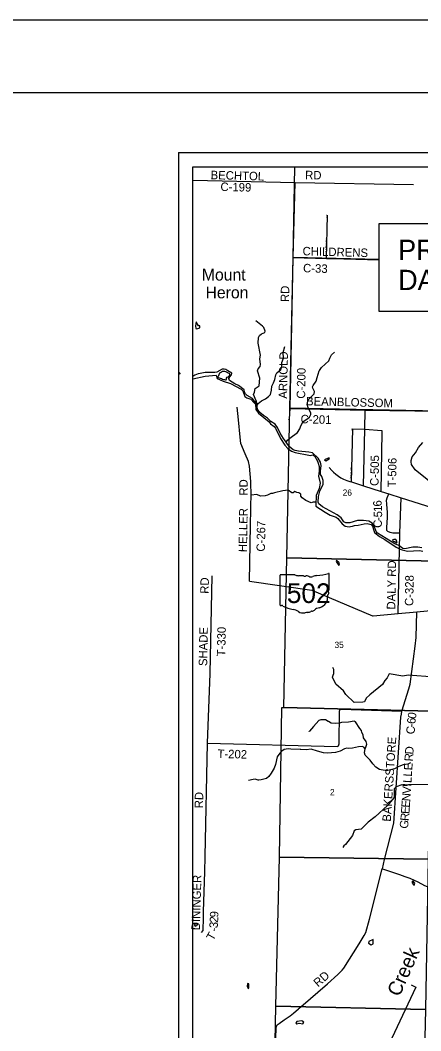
# Model space of a CAD drawing. Extents: x -784 to 1375, y -225 to 440.
# Drawn here: x 215.1 to 270.5, y 300.2 to 440 of the extents above; entities that cross this region are included whole.
import ezdxf

# ---------------------------------------------------------------- set-up
doc = ezdxf.new("R2010")
doc.units = 0
for name, color, linetype in [('GM_X_County_Road', 7, 'Continuous'), ('GM_X_County_Road_Text', 7, 'Continuous'), ('GM_X_County_Subdivision', 7, 'Continuous'), ('GM_X_County_Subdivision_Text', 7, 'Continuous'), ('GM_X_Major_River', 7, 'Continuous'), ('GM_X_Minor_Lake', 7, 'Continuous'), ('GM_X_Minor_River', 7, 'Continuous'), ('GM_X_Minor_River_Text', 7, 'Continuous'), ('GM_X_Section', 7, 'Continuous'), ('GM_X_Section_Text', 7, 'Continuous'), ('GM_X_State_Location', 7, 'Continuous'), ('GM_X_State_Route', 7, 'Continuous'), ('GM_X_State_Shield', 7, 'Continuous'), ('GM_X_Township_Road', 7, 'Continuous'), ('GM_X_Township_Road_Text', 7, 'Continuous'), ('GM_X_Township_Subdivision', 7, 'Continuous'), ('GM_X_Township_Subdivision_Text', 7, 'Continuous'), ('GM_X_Unincorporated_Text', 7, 'Continuous'), ('SH_Border', 7, 'Continuous'), ('SH_Cut_Line', 7, 'Continuous'), ('SH_Data', 7, 'Continuous'), ('SH_Text', 7, 'Continuous')]:
    doc.layers.add(name, color=color, linetype=linetype)

msp = doc.modelspace()

# ---------------------------------------------------------------- linework, layer by layer
at = {"layer": 'GM_X_County_Road'}
msp.add_line((258.21, 407.02), (264.75, 406.84), dxfattribs=at)
for points in [[(238.96, 417.89), (253.09, 417.56), (269.46, 417.26)], [(252.23, 384.67), (252.32, 384.82), (252.4, 386.29), (252.84, 407.18), (253.09, 417.56)], [(252.84, 407.18), (257.42, 407.04), (258.21, 407.02), (258.21, 407.02)], [(246.81, 362.4), (246.93, 370.09), (247.01, 374.7), (246.99, 375.62), (246.99, 376.17), (246.79, 378.31), (246.65, 378.96), (246.18, 380.02), (245.58, 381.44), (245.49, 382.33), (245.28, 384.72), (245.08, 386.47)], [(252.4, 386.29), (262.79, 386.04), (273.08, 385.89), (283.53, 385.61)], [(262.58, 375.57), (262.75, 383.41), (262.79, 386.04)], [(267.58, 369.03), (266.61, 369.04), (266.26, 369.11), (265.95, 369.28), (265.8, 369.39), (265.8, 369.83), (265.87, 371.18), (265.86, 371.9), (265.78, 373.04), (265.73, 373.58), (265.82, 373.94), (266.06, 374.48)], [(267.37, 357.91), (267.58, 369.03), (267.75, 373.93)], [(265.18, 322.58), (265.46, 323.89), (266.77, 328.89), (267.74, 343.59), (267.82, 343.99), (267.88, 344.4), (268.82, 347.5), (269, 348.12), (269.69, 353.42), (269.85, 354.58), (269.94, 358.16)], [(253.64, 303.3), (253.88, 303.51), (257.58, 306.7), (258.99, 307.97), (259.63, 308.56), (259.86, 308.84), (261.96, 312.21), (262.66, 313.36), (262.87, 313.77), (263.4, 315.64), (265.15, 322.57), (265.18, 322.58), (267.52, 321.79), (268.28, 321.53), (268.96, 321.29), (269.55, 321.03), (270.07, 320.79), (271.02, 320.31), (271.59, 320.05), (272.07, 319.91), (278.91, 319.43)], [(250.27, 293.21), (250.49, 300.64), (250.51, 300.8), (250.62, 301), (250.89, 301.21), (251.6, 301.69), (252.41, 302.27), (252.86, 302.63), (253.55, 303.23), (253.64, 303.3)]]:
    msp.add_lwpolyline(points, dxfattribs=at)
at = {"layer": 'GM_X_County_Subdivision'}
msp.add_lwpolyline([(257.42, 407.04), (257.59, 413.01)], dxfattribs=at)
at = {"layer": 'GM_X_Major_River'}
for p, q in [((237, 391.27), (237.19, 391.01)), ((247.75, 386.98), (247.55, 387.18))]:
    msp.add_line(p, q, dxfattribs=at)
for points in [[(247.55, 387.18), (247.19, 387.67), (246.45, 388.09), (246.22, 388.31), (246.12, 388.58), (246.05, 388.84), (245.27, 389.45), (244.77, 389.69), (244.03, 390.16), (243.92, 390.42), (244.06, 390.67), (244.31, 390.92), (244.36, 391.16), (243.81, 391.48), (243.53, 391.66), (243.28, 391.73), (243.01, 391.72), (242.25, 391.29), (241.98, 391.24), (240.68, 391.24), (239.96, 391.13), (239.7, 391.06), (239.23, 390.9), (238.96, 390.69)], [(238.96, 390.4), (240.66, 390.74), (242.18, 390.9), (242.32, 390.44), (243.14, 390.08), (244.16, 389.74), (245.64, 388.96), (245.87, 388.72), (246.15, 387.96), (246.43, 387.77), (246.96, 387.59), (247.41, 387.13), (247.6, 386.88), (247.66, 386.16), (248.02, 385.64), (249.53, 384.44), (249.71, 384.18), (250.2, 383.81), (250.4, 383.58), (251.09, 382.12), (251.66, 381.19), (252.11, 380.74), (252.59, 380.4), (253.12, 380.19), (254.99, 379.81), (255.25, 379.78), (255.53, 379.88), (255.76, 379.71), (256.18, 379), (256.31, 378.72), (256.42, 378.24), (256.45, 377.67), (256.34, 376.91), (256.55, 375.95), (256.45, 375.2), (256.01, 374.24), (255.95, 372.97), (255.99, 372.75), (257.24, 371.95), (257.96, 371.53), (258.8, 371.24), (259.02, 371.08), (259.6, 370.32), (260.04, 370.01), (260.57, 369.92), (260.78, 369.94), (261.03, 370.01), (261.32, 370.11), (261.83, 370.15), (262.65, 370.34), (263.09, 370.36), (263.64, 370.21), (263.8, 369.99), (263.99, 369.38), (264.09, 369.14), (264.78, 368.56), (265.5, 368.16), (267.06, 367.11), (267.64, 366.84), (267.92, 366.71), (268.67, 366.53), (270.29, 366.63), (270.79, 366.55)], [(244.08, 391.09), (243.87, 391.17), (243.76, 391.22), (243.62, 391.29), (243.51, 391.36), (243.39, 391.4), (243.23, 391.41), (243.06, 391.38), (242.94, 391.31), (242.77, 391.22), (242.65, 391.16), (242.58, 391.06), (242.53, 390.96), (242.49, 390.82), (242.47, 390.72), (242.42, 390.65), (242.43, 390.55), (242.59, 390.5), (242.74, 390.46), (242.9, 390.41), (243.05, 390.35), (243.2, 390.29), (243.35, 390.27)], [(243.35, 390.27), (243.46, 390.24), (243.56, 390.26), (243.61, 390.35), (243.63, 390.47), (243.68, 390.6), (243.82, 390.67), (243.91, 390.74), (244, 390.82), (244.05, 390.9), (244.08, 391.09)], [(247.75, 386.98), (247.55, 387.18), (247.71, 387.34)], [(247.71, 387.34), (247.75, 386.98)], [(256.9, 372.66), (256.39, 373.08), (256.3, 373.34), (256.34, 374.12), (256.53, 374.86), (257, 375.81), (256.98, 376.31), (256.78, 376.88), (256.63, 377.15), (256.62, 377.61), (256.71, 378.39), (256.59, 378.84), (256.29, 379.41), (255.52, 380.13), (254.99, 380.25), (253.56, 380.39), (253.1, 380.46), (252.81, 380.57), (252.27, 381.03), (251.65, 381.94), (251.51, 382.14), (251.02, 382.86), (250.66, 383.66), (250.32, 384.12), (249.74, 384.47), (249.27, 384.95), (248.74, 385.33), (248.2, 385.72), (247.92, 386.21), (247.79, 386.93), (247.75, 386.98)], [(270.61, 367), (270.09, 367.1), (269.38, 367.08), (268.3, 366.87), (268.02, 366.92), (267.47, 367.34), (266.91, 367.54), (264.49, 369.05), (264.3, 369.26), (264.09, 369.9), (263.76, 370.42), (263.55, 370.56), (263.31, 370.67), (262.55, 370.79), (261.75, 370.77), (260.69, 370.45), (260.11, 370.47), (259.84, 370.62), (259.46, 371.16), (258.93, 371.57), (256.9, 372.66)]]:
    msp.add_lwpolyline(points, dxfattribs=at)
at = {"layer": 'GM_X_Minor_Lake'}
for points in [[(239.43, 398.29), (239.31, 397.72), (239.35, 397.35), (239.49, 397.31), (239.9, 397.45)], [(239.9, 397.45), (239.93, 397.71), (239.73, 397.71), (239.43, 398.29)], [(257.82, 379.3), (257.84, 379.42), (257.69, 379.42), (257.17, 379.16)], [(257.17, 379.16), (257.37, 379.06), (257.82, 379.3)], [(267.02, 368.14), (266.75, 368.17), (266.59, 368.11), (266.65, 367.94), (266.91, 367.88)], [(266.91, 367.88), (267.13, 367.68), (267.21, 367.83), (267.02, 368.14)], [(258.84, 365.23), (258.8, 365.11), (259.14, 364.57)], [(259.14, 364.57), (259.25, 364.75), (259.2, 364.93), (258.84, 365.23)], [(269.37, 320.93), (269.24, 320.75), (269.47, 320.39), (269.59, 320.33)], [(269.59, 320.33), (269.64, 320.59), (269.37, 320.93)], [(239.51, 315.02), (239.12, 314.87), (239.28, 314.64)], [(239.28, 314.64), (239.6, 314.78), (239.51, 315.02)], [(263.24, 312.31), (263.61, 312.08), (263.88, 312.21), (263.89, 312.81)], [(263.89, 312.81), (263.3, 312.53), (263.24, 312.31)], [(246.72, 306.7), (246.52, 306.75), (246.45, 306.38), (246.61, 306.03)], [(246.61, 306.03), (246.68, 306.1), (246.72, 306.7)], [(254.29, 301.4), (254.03, 301.57), (253.34, 301.46), (253.2, 301.22)], [(253.2, 301.22), (253.33, 301.17), (253.68, 301.26), (254.16, 301.16), (254.29, 301.4)]]:
    msp.add_lwpolyline(points, dxfattribs=at)
at = {"layer": 'GM_X_Minor_River'}
for points in [[(248.01, 391.76), (248.26, 392.11), (248.3, 392.38), (248.23, 393.14), (248.3, 393.66), (247.98, 395.3), (248.02, 396.11), (248.19, 396.39), (248.45, 396.62), (248.89, 396.78), (248.96, 396.98), (248.77, 397.47), (248.61, 397.68), (247.68, 398.39)], [(251.14, 391.69), (251.25, 392.1), (251.26, 392.63), (251.51, 393.26), (251.46, 394.01), (251.67, 394.87)], [(256.46, 391.56), (256.74, 391.93), (257.75, 392.87), (257.91, 393.23), (257.94, 393.35), (258.15, 393.69), (258.54, 394.08)], [(247.71, 387.34), (247.33, 388.2), (247.49, 388.53), (247.59, 389.06), (248.12, 389.41), (248.24, 390.48), (247.88, 391.49), (248.01, 391.76)], [(247.83, 386.73), (248.01, 386.97), (248.47, 387.36), (249.01, 387.64), (249.42, 387.94), (249.71, 388.23), (249.84, 388.82), (249.88, 389.38), (250.11, 389.83), (250.29, 390.29), (250.44, 390.96), (250.57, 391.2), (251.14, 391.69)], [(251.87, 381.6), (252.03, 381.89), (252.39, 382.18), (253.42, 382.95), (253.74, 383.47), (253.89, 383.88), (254.21, 384.46), (254.74, 384.82), (255.09, 385.08), (255.26, 385.43), (255.26, 385.67), (254.9, 386.39), (254.79, 386.82), (254.87, 387.29), (255.06, 387.66), (255.19, 387.77), (255.24, 387.82), (255.72, 388.33), (255.78, 388.63), (255.53, 389.1), (255.52, 389.28), (255.61, 389.45), (256.02, 390.05), (256.17, 390.56), (256.44, 391.47), (256.46, 391.56)], [(273.03, 375.13), (269.69, 377.79), (269.2, 378.55), (269.14, 378.89), (269.14, 379.1), (269.3, 379.59), (269.75, 380.16), (270.15, 380.89), (270.79, 381.59)], [(255.97, 373.33), (255.61, 373.34), (255.34, 373.23), (254.57, 373.57), (254.07, 373.9), (253.91, 374.17), (253.91, 374.45), (253.62, 374.59), (253.35, 374.64), (253.08, 374.81), (252.83, 374.63), (252.63, 374.6), (252.14, 374.99), (251.42, 374.9), (250.26, 374.63), (249.99, 374.51), (249.73, 374.51), (249.26, 374.31), (248.96, 374.18), (248.34, 374.13), (247.75, 374.36), (247.05, 374.3)], [(283.47, 347.41), (278.09, 347.44), (278.04, 348.56), (272.49, 348.8), (272.38, 349.1), (268.73, 349.39), (267.98, 349.26), (266.12, 349.59), (265.83, 349.02), (265.5, 348.67), (265.18, 348.08), (263.45, 346.68), (262.95, 346.19), (262.71, 345.72), (262.45, 345.64), (261.28, 345.61), (260.13, 346.69), (259.81, 347.22), (258.74, 348.12), (258.28, 349.09), (258.37, 349.4), (258.46, 349.61), (258.47, 350.17), (258.31, 350.46)], [(269.07, 337.25), (268.71, 337.06), (268.05, 336.96), (267.43, 336.74), (266.84, 336.41), (265.92, 336.21), (265.56, 336.19), (265.02, 336.28), (264.76, 336.34), (264.27, 336.65), (263.83, 337.12), (263.47, 337.63), (262.79, 338.34), (262.72, 338.64), (262.8, 339.23), (262.83, 339.27), (263.02, 339.83), (262.94, 340.19), (262.57, 340.73), (262.52, 341.12), (262.32, 341.46), (262.29, 341.73), (262.07, 342), (261.45, 342.92), (261.29, 343.02), (260.48, 342.88), (259.53, 342.85), (259.26, 342.74), (258.72, 342.69), (258.09, 342.76), (257.72, 342.96), (257.66, 342.99), (257.32, 343.2), (256.67, 343.21), (256.4, 343.12), (255.66, 342.29), (255.07, 341.64), (255.06, 341.59), (255.04, 341.63)], [(262.8, 339.19), (262.6, 339.44), (262.4, 339.54), (261.87, 339.45), (261.05, 339.29), (260.51, 339.25), (260.26, 339.29), (259.92, 339.2), (259.33, 338.87), (258.67, 338.68), (257.58, 338.6), (257.05, 338.63), (256.19, 338.87), (255.32, 339.16), (254.61, 339.07), (253.87, 339.11), (253.82, 339.1), (252.52, 339.17), (252.12, 339.18), (251.58, 339.1), (251.25, 338.88), (250.98, 338.6), (250.63, 338.08), (250.39, 337.05), (250.19, 336.51), (249.79, 335.85), (249.47, 335.37), (249.15, 335.1), (248.41, 334.9), (248.08, 334.87), (248.01, 334.88), (247.59, 335.01), (247.29, 334.96), (246.64, 334.8)], [(276.95, 334.07), (271.69, 334.25), (268.78, 334.23), (268.52, 334.1), (268.09, 334.1), (267.85, 334.22), (267.06, 333.96), (266.81, 333.68), (266.81, 333.03), (266.8, 332.45), (265.87, 331.35), (264.17, 329.8), (263.2, 329.03), (262.25, 328.1), (261.52, 328.01), (261.27, 327.87), (261.02, 327.21), (260.09, 325.97), (259.84, 325.78), (259.71, 325.56)], [(269.16, 306.54), (269.81, 306.22), (264.99, 296.05), (273.4, 295.29), (274.11, 295.19)]]:
    msp.add_lwpolyline(points, dxfattribs=at)
at = {"layer": 'GM_X_Section'}
for points in [[(264.75, 406.89), (252.84, 407.17), (253.06, 419.71)], [(273.35, 399.71), (273.04, 385.92), (252.38, 386.32), (252.84, 407.17), (264.75, 406.89)], [(250.06, 283.71), (250.45, 303.6), (271.13, 303.11), (270.68, 283.71)]]:
    msp.add_lwpolyline(points, dxfattribs=at)
for points in [[(252.38, 386.32), (273.04, 385.92), (272.6, 365.18), (251.94, 365.64)], [(251.94, 365.64), (272.6, 365.18), (272.39, 344.42), (271.94, 344.41), (251.52, 344.93)], [(251.52, 344.93), (271.94, 344.41), (271.52, 323.91), (250.93, 324.19), (251.25, 344.93)], [(250.93, 324.19), (271.52, 323.91), (271.13, 303.11), (250.45, 303.6)]]:
    msp.add_lwpolyline(points, close=True, dxfattribs=at)
at = {"layer": 'GM_X_State_Route'}
for points in [[(257.83, 378.1), (258.17, 377.7), (258.42, 377.46), (258.74, 377.19), (259.09, 376.92), (259.44, 376.69), (259.79, 376.51), (260.25, 376.32), (260.68, 376.18)], [(260.68, 376.18), (260.88, 376.12), (262.58, 375.57), (265.01, 374.8), (266.06, 374.48), (267.75, 373.93), (272.91, 372.3), (275.85, 371.43), (280.11, 370.15), (281.81, 369.65), (282.52, 369.43), (283.13, 369.24), (283.52, 369.12), (283.97, 368.97), (284.7, 368.66), (285.29, 368.39), (286.01, 368.09), (286.04, 368.07)], [(246.81, 362.4), (255.42, 361.16), (263.82, 357.61)], [(263.82, 357.61), (263.91, 357.58), (267.37, 357.91), (269.94, 358.16), (274.24, 358.56), (276.35, 358.62), (283.69, 358.3), (283.73, 358.3)]]:
    msp.add_lwpolyline(points, dxfattribs=at)
at = {"layer": 'GM_X_State_Shield'}
for p, q in [((251.01, 363.21), (251.01, 359.08)), ((253.07, 363.28), (251.08, 363.28)), ((257.81, 361.23), (257.81, 363.38)), ((257.81, 361.23), (257.81, 361.23))]:
    msp.add_line(p, q, dxfattribs=at)
for centre, major_axis, start_param, end_param in [((251.09, 363.22), (0.0788, 0), 1.712693, 3.28349), ((253.55, 363.76), (0.764, 0), 4.042523, 4.731795), ((253.8, 360.96), (2.74, 0), 1.404758, 1.657858), ((254.42, 363.24), (0.22, 0), 3.836095, 5.185415), ((254.74, 362.76), (0.458, 0), 0.950623, 2.079405), ((255.34, 363.42), (0.551, 0), 4.081561, 5.145723), ((256.31, 362.02), (1.45, 0), 1.699011, 2.107814), ((255.39, 368.91), (7.21, 0), 4.814394, 5.042369), ((257.74, 363.39), (0.0757, 0), 6.141152, 7.989035), ((257.79, 361.07), (0.117, 0), 1.883978, 3.671073), ((257.05, 360.79), (0.703, 0), 5.934695, 6.695948), ((257.73, 361.22), (0.081, 0), 5.05454, 6.418171), ((255.79, 360.05), (1.8, 0), 5.101752, 6.440018), ((258.08, 360.32), (0.511, 0), 2.387724, 3.262537), ((251.09, 359.07), (0.0794, 0), 3.00124, 4.508301), ((251.1, 359.5), (0.606, 0), 4.665946, 4.897461), ((251.23, 358.85), (0.219, 0), 0.519207, 1.627899), ((253.99, 362.55), (5.21, 0), 4.195997, 4.488961), ((252.44, 357.23), (1.63, 0), 0.823519, 1.323587), ((254.2, 358.82), (1.03, 0), 4.026481, 4.996735), ((254.8, 357.4), (0.849, 0), 1.495662, 1.94098), ((254.87, 358.52), (0.551, 0), 4.691044, 5.507374), ((255.37, 358.12), (0.155, 0), 1.147584, 2.315152), ((255.3, 358.68), (0.583, 0), 4.937069, 5.64225), ((256.55, 357.92), (0.988, 0), 1.647645, 2.488434)]:
    msp.add_ellipse(centre, major_axis=major_axis, ratio=0.8, start_param=start_param, end_param=end_param, dxfattribs=at)
at = {"layer": 'GM_X_Township_Road'}
for points in [[(262.75, 383.41), (265.09, 383.24)], [(265.01, 374.8), (265.15, 382.98), (265.15, 383.12), (265.09, 383.24)], [(241, 339.99), (241.35, 349.63), (241.63, 363.15)], [(241, 339.99), (258.94, 339.54), (259.12, 339.62), (259.2, 339.87), (259.25, 344.42), (259.3, 344.59), (259.42, 344.68), (267.88, 344.4)], [(240.67, 324.32), (241, 339.99)], [(240.61, 322.2), (240.61, 322.2), (240.67, 324.32)], [(240.45, 316.67), (240.45, 316.68), (240.61, 322.2)], [(240.43, 315.82), (240.43, 315.83), (240.45, 316.67)], [(240.14, 313.78), (240.38, 314.07), (240.43, 315.82)]]:
    msp.add_lwpolyline(points, dxfattribs=at)
at = {"layer": 'GM_X_Township_Subdivision'}
msp.add_lwpolyline([(260.88, 376.12), (261.1, 383.45), (262.75, 383.41)], dxfattribs=at)
at = {"layer": 'SH_Border'}
msp.add_lwpolyline([(30, 430), (670, 430), (670, 10), (30, 10)], close=True, dxfattribs=at)
at = {"layer": 'SH_Cut_Line'}
msp.add_lwpolyline([(0, 0), (680, 0), (680, 440), (0, 440)], close=True, dxfattribs=at)
at = {"layer": 'SH_Data'}
for q in [(376.96, 421.71), (236.96, 281.71)]:
    msp.add_line((236.96, 421.71), q, dxfattribs=at)
at = {"layer": 'SH_Text'}
for points in [[(238.96, 419.71), (374.96, 419.71), (374.96, 283.71), (238.96, 283.71)], [(264.75, 411.86), (311.75, 411.86), (311.75, 399.71), (264.75, 399.71)]]:
    msp.add_lwpolyline(points, close=True, dxfattribs=at)

# ---------------------------------------------------------------- texts
at = {"layer": 'GM_X_County_Road_Text'}
for s, height, rotation, p in [('BECHTOL', 1.172, 358.5085, (241.4, 418.01)), ('RD', 1.172, 359.0128, (254.48, 418)), ('C-199', 1.172, 358.6237, (242.76, 416.38)), ('CHILDRENS', 1.172, 358.4088, (254.12, 407.48)), ('C-33', 1.172, 358.2847, (254.19, 405.13)), ('RD', 1.172, 89.0123, (252.26, 401)), ('ARNOLD', 1.172, 88.8443, (251.98, 387.63)), ('C-200', 1.172, 88.8981, (254.48, 387.63)), ('BEANBLOSSOM', 1.1719, 358.6183, (254.6, 386.72)), ('C-201', 1.172, 358.6227, (253.85, 384.24)), ('C-505', 1.172, 88.8984, (264.64, 375.55)), ('RD', 1.172, 90.4761, (246.56, 374.23)), ('6', 1.17, 93.9716, (265.1, 372.75)), ('HELLER', 1.172, 89.102, (246.44, 366.4)), ('1', 1.17, 92.5688, (265.14, 372.01)), ('5', 1.17, 89.0163, (265.13, 371.21)), ('C-267', 1.172, 89.1736, (248.93, 366.47)), ('C', 1.17, 88.1707, (265.08, 369.75)), ('-', 1.17, 87.6183, (265.11, 370.7)), ('DALY RD', 1.172, 88.9103, (266.95, 358.46)), ('C-328', 1.172, 89.1736, (269.45, 358.95)), ('0', 1.17, 80.3697, (269.79, 343.29)), ('6', 1.17, 85.0928, (269.73, 342.6)), ('-', 1.17, 86.0311, (269.69, 342.13)), ('C', 1.17, 86.2038, (269.63, 341.18)), ('BAKERSSTORE', 1.1719, 86.2308, (266.33, 329.09)), ('R', 1.17, 86.2036, (269.38, 337.43)), ('D', 1.17, 86.2046, (269.45, 338.39)), ('E', 1.17, 86.205, (269.3, 336.19)), ('L', 1.17, 86.2034, (269.24, 335.32)), ('I', 1.17, 86.2036, (269.15, 333.96)), ('L', 1.17, 86.205, (269.19, 334.44)), ('N', 1.17, 86.2046, (269.02, 331.91)), ('V', 1.17, 86.2046, (269.08, 332.93)), ('E', 1.17, 86.1951, (268.96, 331.03)), ('R', 1.17, 85.637, (268.82, 329.18)), ('E', 1.17, 86.0955, (268.9, 330.15)), ('G', 1.17, 82.1827, (268.68, 328.09)), ('RD', 1.172, 41.2759, (256.27, 306.17))]:
    msp.add_text(s, height=height, rotation=rotation, dxfattribs=at).set_placement(p)
at = {"layer": 'GM_X_County_Subdivision_Text'}
for s, rotation, p in [('DR', 90, (257.56, 412.71)), ('RAVENWOOD', 88.1122, (257.42, 408))]:
    msp.add_text(s, height=0.195, rotation=rotation, dxfattribs=at).set_placement(p)
at = {"layer": 'GM_X_Minor_River_Text'}
msp.add_text('Creek', height=1.957, rotation=66.0051, dxfattribs=at).set_placement((267.53, 304.79))
at = {"layer": 'GM_X_Section_Text'}
for s, p in [('26', (259.68, 374.21)), ('35', (258.55, 353.15)), ('2', (257.93, 332.78))]:
    msp.add_text(s, height=0.863, rotation=0, dxfattribs=at).set_placement(p)
at = {"layer": 'GM_X_State_Location'}
for s in ['s', 'r']:
    msp.add_text(s, height=0.00391, dxfattribs=at).set_placement((254.34, 360.87))
msp.add_text('502', height=0.00391, rotation=0, dxfattribs=at).set_placement((252.96, 360.59))
at = {"layer": 'GM_X_State_Shield'}
msp.add_text('502', height=2.719, dxfattribs=at).set_placement((251.95, 359.37))
at = {"layer": 'GM_X_Township_Road_Text'}
for s, height, rotation, p in [('T-506', 1.172, 88.8768, (267.06, 375.36)), ('RD', 1.172, 89.0123, (241.14, 360.64)), ('SHADE', 1.172, 88.9696, (240.93, 350.64)), ('T-330', 1.172, 88.8768, (243.44, 351.97)), ('T-202', 1.172, 358.5967, (242.35, 337.94)), ('RD', 1.172, 89.0123, (240.36, 330.96)), ('DININGER', 1.172, 88.2945, (239.92, 314.09)), ('9', 1.17, 88.0641, (242.47, 315.85)), ('3', 1.17, 85.7913, (242.38, 314.35)), ('2', 1.17, 87.5546, (242.44, 315.11)), ('T', 1.17, 60.5138, (241.76, 312.56)), ('-', 1.17, 86.7829, (242.36, 313.88))]:
    msp.add_text(s, height=height, rotation=rotation, dxfattribs=at).set_placement(p)
at = {"layer": 'GM_X_Township_Subdivision_Text'}
for s, rotation, p in [('D', 86.665, (261.07, 383.16)), ('R', 86.6654, (261.08, 383.34)), ('WOODLANE', 87.8529, (260.86, 376.57))]:
    msp.add_text(s, height=0.195, rotation=rotation, dxfattribs=at).set_placement(p)
at = {"layer": 'GM_X_Unincorporated_Text'}
for s, p in [('Mount', (240.2, 403.98)), ('Heron', (240.71, 401.52))]:
    msp.add_text(s, height=1.629, rotation=0, dxfattribs=at).set_placement(p)
at = {"layer": 'SH_Text'}
for s, p in [('PROJECT LOCATION:', (267.35, 406.83)), ('DAR-121-18.71', (267.35, 402.67))]:
    msp.add_text(s, height=2.8, dxfattribs=at).set_placement(p)

doc.saveas('drawing.dxf')
